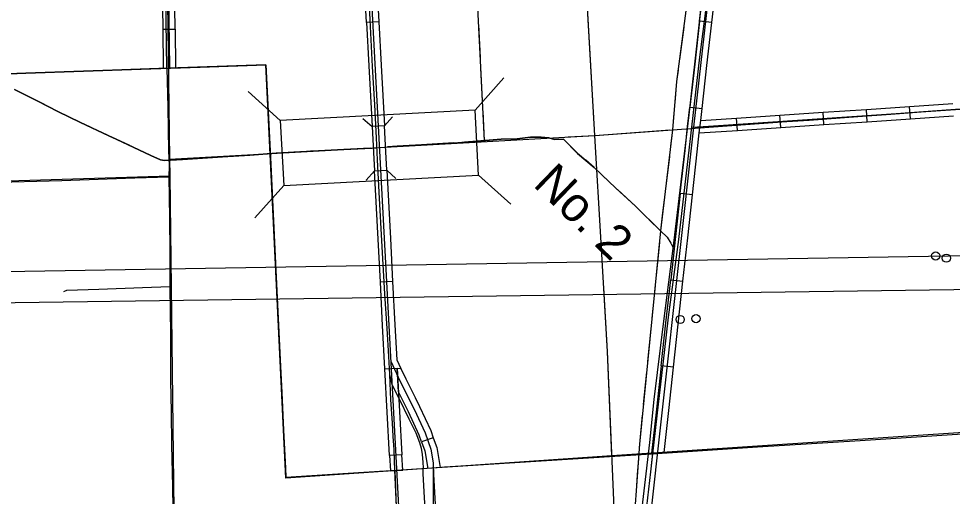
# Model space of a CAD drawing. Extents: x 646058 to 725608, y 1473014 to 1561048.
# Drawn here: x 656968 to 662655, y 1553726 to 1556632 of the extents above; entities that cross this region are included whole.
import ezdxf

# ---------------------------------------------------------------- set-up
doc = ezdxf.new("R2010")
doc.units = 0
doc.layers.add('Default', color=7, linetype='Continuous')

msp = doc.modelspace()

# ---------------------------------------------------------------- linework, layer by layer
at = {"layer": 'Default'}
for p, q in [((659161.9, 1556613.6), (659087, 1556609.6)), ((659087, 1556609.6), (659087, 1556609.6)), ((661190.6, 1556609.3), (661116.1, 1556617.8)), ((661190.6, 1556609.3), (661190.6, 1556609.3)), ((657845.8, 1556567.9), (657920.8, 1556569)), ((659747.9, 1556075.7), (659924.3, 1556272)), ((658561.5, 1556012.5), (658365.2, 1556189)), ((661056.4, 1556093.2), (661130.9, 1556084.7)), ((662136.5, 1556005.2), (662131.5, 1556080.1)), ((662399.9, 1556022.8), (662394.9, 1556097.6)), ((661346.3, 1555952.5), (661341.3, 1556027.4)), ((661609.7, 1555970.1), (661604.7, 1556044.9)), ((661873.1, 1555987.7), (661868.1, 1556062.5)), ((659158.3, 1555977.2), (659158.3, 1555977.2)), ((659172.6, 1555707.3), (659172.6, 1555707.3)), ((659172.6, 1555707.3), (659172.6, 1555707.3)), ((659172.6, 1555707.3), (659172.6, 1555707.3)), ((659172.6, 1555707.3), (659172.6, 1555707.3)), ((659172.6, 1555707.3), (659172.6, 1555707.3)), ((659172.6, 1555707.3), (659172.6, 1555707.3)), ((659172.6, 1555707.3), (659172.6, 1555707.3)), ((659768.9, 1555680.3), (659965.3, 1555503.8)), ((658582.6, 1555617.1), (658406.1, 1555420.7)), ((661072.5, 1555560.1), (660998, 1555568.3)), ((659246.2, 1555031.8), (659171.3, 1555027.8)), ((660940, 1555043.5), (661014.6, 1555035.3)), ((659199.3, 1554500.6), (659274.2, 1554504.6)), ((660956.6, 1554510.5), (660882.1, 1554518.7)), ((659493.4, 1554082), (659422.7, 1554057.1)), ((659302.3, 1553977.3), (659227.4, 1553973.3)), ((660823.4, 1553987.7), (660899.4, 1553992.7))]:
    msp.add_line(p, q, dxfattribs=at)
for points in [[(657836.4, 1559731.1), (657852.6, 1558422.3), (657853.7, 1558332.9), (657886.7, 1555776.3), (657888, 1555674.8), (657919.2, 1553129.9), (657922.4, 1553034.6), (657948.9, 1552246.6), (657964.6, 1551804.3), (657962.8, 1550661.1), (657966.7, 1550505.3), (657969.3, 1550400.1), (657996.7, 1547841.2)], [(658953.8, 1559731.1), (659024.8, 1558484.7), (659297.5, 1553362.2)], [(661474.1, 1559731.1), (661439.7, 1559417.2), (661367.6, 1558733.9), (661308.2, 1558296.7), (661244.5, 1557694.1), (661185.1, 1557210.2), (661113, 1556611.8), (661049.3, 1556047.3), (660956, 1555266.4), (660896.6, 1554791), (660837.2, 1554315.6), (660809.9, 1554053.3), (660737.8, 1553429.4)], [(660803.4, 1553465), (661080.3, 1555972.4), (661383.8, 1558638), (661511.3, 1559731.1)], [(657958.2, 1559412.7), (657923, 1559397.8), (657897.3, 1559383.2), (657874.8, 1559362.2), (657858.8, 1559337.7), (657849.4, 1559313.4), (657845.7, 1559274.7), (657858.7, 1558454.5), (657870.9, 1558422.7), (657854.2, 1558362.1), (657858, 1558328.5), (657886.7, 1556334.8)], [(660830.5, 1553984.9), (660865.7, 1554286.1), (660902.5, 1554601.2), (660927.1, 1554815.2), (660989.2, 1555288.6), (661021.8, 1555570.5), (661068, 1555972.4), (661117.1, 1556398.1), (661151.1, 1556664.1), (661188.7, 1556982.2), (661216.2, 1557225.8), (661259.5, 1557598), (661287, 1557848.1), (661328.2, 1558239.9), (661359.2, 1558512.4), (661372.2, 1558630.2)], [(660478.2, 1555921.9), (660325.5, 1558577.4)], [(661255.9, 1558579.7), (661149.5, 1557665.2), (661089.3, 1557112.2), (660975.9, 1556250.8), (660951, 1555956.5), (660877.8, 1555340.5), (660749, 1554042.3), (660702.9, 1553393.6)], [(659298.3, 1558455.1), (659610.9, 1558118.4), (659660.7, 1558057.1), (659689.4, 1558003.4), (659709.8, 1557937.6), (659713.2, 1557712.2), (659803.4, 1555890)], [(657871.2, 1556330.8), (657867.4, 1556616.5), (657867.4, 1556775.6), (657867.4, 1556951.3), (657863.6, 1557090.1), (657859.9, 1557343.5), (657856.1, 1557581.8), (657853.1, 1557835.9), (657851.6, 1557945.2), (657847, 1558131.5), (657844.8, 1558301.9), (657839.5, 1558321.5)], [(660478.2, 1555921.9), (660370.7, 1557790.5)], [(659089.9, 1556955.3), (659107.2, 1556624.8), (659121.3, 1556340.9), (659135.4, 1556106.9), (659146.2, 1555906.4), (659152.7, 1555773.1), (659162.4, 1555575.9), (659179.8, 1555243.2), (659196, 1554958.2), (659210.1, 1554746.9), (659220.9, 1554575.7), (659227.4, 1554466.2), (659241.5, 1554406.6), (659285.9, 1554318.8), (659344.5, 1554197.5), (659386.7, 1554111.9), (659410.5, 1554053.3), (659420.3, 1554018.7), (659426.8, 1553979.7), (659430, 1553934.1), (659432.1, 1553896.1)], [(659147.9, 1556877.2), (659161.9, 1556613.6)], [(661116.1, 1556617.8), (661146, 1556880.1)], [(657842, 1556831.8), (657845.8, 1556567.9)], [(657920.8, 1556569), (657917, 1556832.9)], [(659087, 1556609.6), (659073, 1556873.2)], [(661190.6, 1556609.3), (661220.5, 1556871.7)], [(659087, 1556609.6), (659101.1, 1556345.9)], [(659161.9, 1556613.6), (659176, 1556349.9)], [(659768.6, 1556594.3), (659778.4, 1556396.5)], [(661116.1, 1556617.8), (661086.2, 1556355.5)], [(661160.7, 1556347), (661190.6, 1556609.3)], [(657845.8, 1556567.9), (657849.2, 1556334.3)], [(657920.8, 1556569), (657924.2, 1556335.4)], [(661019.3, 1556580.8), (660993.5, 1556384.5)], [(665836.1, 1554301.5), (663213.3, 1554145.7), (660581.9, 1553971.7), (658595.4, 1553836.2), (658473.8, 1556351.9), (657879.5, 1556331.1), (656743.7, 1556291.4)], [(656743.7, 1556291.4), (657011.2, 1556300.7), (657713.6, 1556325.3), (658073.8, 1556337.9), (658473.8, 1556351.9), (658501.1, 1555786.6), (658515.6, 1555487.3), (658534.3, 1555101.6), (658562.6, 1554515.9), (658570.2, 1554358.2), (658581.4, 1554127.2), (658592.5, 1553896.2), (658595.1, 1553842.9), (658975.8, 1553867.1), (659204.5, 1553881.6), (659830, 1553921.3), (660344.2, 1553954), (660951, 1553992.6), (661468.1, 1554025.9), (662094.7, 1554066.2), (662560.5, 1554096.2), (663187, 1554136.5)], [(658473.8, 1556351.9), (658073.8, 1556337.9), (657713.6, 1556325.3), (657011.2, 1556300.7), (656792.7, 1556293.1)], [(657871.2, 1556330.8), (657876.4, 1556093.1), (657881.7, 1555828.5), (657884, 1555739.5), (657882.9, 1555670.5)], [(657871.2, 1556330.8), (657876.4, 1556093.1), (657881.7, 1555828.5), (657884, 1555739.5), (657882.9, 1555670.5)], [(658473.8, 1556351.9), (658501.1, 1555786.6), (658515.6, 1555487.3), (658534.3, 1555101.6), (658562.6, 1554515.9), (658581.4, 1554127.2), (658595.1, 1553842.9)], [(659101.1, 1556345.9), (659120.8, 1555975.2)], [(659176, 1556349.9), (659195.7, 1555979.2)], [(659781.6, 1556330.6), (659791.4, 1556132.8)], [(660984.8, 1556319), (660975.9, 1556250.8), (660965, 1556122.1)], [(661086.2, 1556355.5), (661056.4, 1556093.2)], [(661130.9, 1556084.7), (661160.7, 1556347)], [(659108.6, 1555844.2), (658949, 1555835.1), (658793.6, 1555828.7), (658537.1, 1555813.3), (658375.2, 1555801.1), (658209.3, 1555791.4), (657966.4, 1555775.2), (657856.4, 1555769.6), (657832.1, 1555773.6), (657773.8, 1555799.5), (657562.6, 1555898.3), (657517.2, 1555919.3), (657345.6, 1556000.3), (657206.4, 1556066.6), (657085, 1556130.6), (656941.8, 1556200.2)], [(656941.8, 1556200.2), (657085, 1556130.6), (657206.4, 1556066.6), (657345.6, 1556000.3), (657517.2, 1555919.3), (657562.6, 1555898.3), (657773.8, 1555799.5), (657832.1, 1555773.6), (657856.4, 1555769.6), (657966.4, 1555775.2), (658209.3, 1555791.4), (658375.2, 1555801.1), (658537.1, 1555813.3), (658793.6, 1555828.7), (658949, 1555835.1), (659119, 1555844.8), (659273.6, 1555855.4), (659642.7, 1555877.2), (659908.1, 1555898.3), (660003.6, 1555901.5), (660085.4, 1555911.2), (660151, 1555912), (660197.1, 1555907.2), (660231.1, 1555896.7), (660286.9, 1555899.1), (660372.7, 1555812.5), (660473.1, 1555727.5), (660605.8, 1555601.2), (660724.8, 1555490.3), (660877.8, 1555340.5), (660917.4, 1555302.5), (660940.1, 1555266.9), (660952.9, 1555241.6)], [(661080.3, 1555972.4), (663126.4, 1556108.9), (664476.5, 1556202.7), (664477.5, 1556111.4), (664473.4, 1556093.2), (664466.3, 1556074.5), (664457.6, 1556060.7), (664437.5, 1556041.2), (663835.5, 1555479), (663817, 1555457), (663805.5, 1555435.1), (663801.3, 1555418), (663800.3, 1555398.9), (663879.7, 1554193.6), (663889.9, 1554159.1), (663917.7, 1553666.2)], [(657168.4, 1556086.7), (657085, 1556130.6), (656991.7, 1556176)], [(660478.2, 1555921.9), (663119, 1556113.2)], [(661027, 1555830.7), (661043.1, 1555976.5), (661056.4, 1556093.2)], [(661067.9, 1555971.8), (661783.2, 1556014.6), (662079.9, 1556036), (662280.3, 1556051.6), (662439.8, 1556064.2), (662732.6, 1556084.7), (662958.3, 1556100.2), (663106.2, 1556109)], [(661122.7, 1556012.8), (661130.9, 1556084.7)], [(661868.1, 1556062.5), (662131.5, 1556080.1)], [(662131.5, 1556080.1), (662394.9, 1556097.6)], [(662394.9, 1556097.6), (662658.3, 1556115.2)], [(657406.1, 1555971.8), (657345.6, 1556000.3), (657227.2, 1556056.7)], [(659065, 1556025.4), (659120.8, 1555975.2)], [(659195.7, 1555979.2), (659245.9, 1556035)], [(659794.7, 1556066.9), (659803.4, 1555890)], [(660959.5, 1556056.3), (660951, 1555956.5), (660939.5, 1555859.3)], [(661122.7, 1556012.8), (661341.3, 1556027.4)], [(661341.3, 1556027.4), (661604.7, 1556044.9)], [(661604.7, 1556044.9), (661868.1, 1556062.5)], [(662136.5, 1556005.2), (662399.9, 1556022.8)], [(662399.9, 1556022.8), (662663.3, 1556040.4)], [(659195.7, 1555979.2), (659120.8, 1555975.2)], [(659120.8, 1555975.2), (659129.2, 1555818.7), (659135.2, 1555705.3)], [(659210.1, 1555709.3), (659204.1, 1555822.7), (659195.7, 1555979.2)], [(661101.5, 1555822.5), (661114.2, 1555937), (661122.7, 1556012.8)], [(661346.3, 1555952.5), (661609.7, 1555970.1)], [(661609.7, 1555970.1), (661873.1, 1555987.7)], [(661873.1, 1555987.7), (662136.5, 1556005.2)], [(657555.4, 1555901.6), (657517.2, 1555919.3), (657465.7, 1555943.6)], [(657886.7, 1555776.3), (660478.2, 1555921.9)], [(660877.8, 1555340.5), (660724.8, 1555490.3), (660605.8, 1555601.2), (660473.1, 1555727.5), (660372.7, 1555812.5), (660286.9, 1555899.1), (660231.1, 1555896.7), (660197.1, 1555907.2), (660151, 1555912), (660085.4, 1555911.2), (660003.6, 1555901.5), (659908.1, 1555898.3), (659642.7, 1555877.2), (659273.6, 1555855.4), (659214.6, 1555851.4)], [(660145.2, 1555912), (660085.4, 1555911.2), (660003.6, 1555901.5), (659947.8, 1555899.6)], [(660315.8, 1555912.8), (660478.2, 1555921.9)], [(660478.2, 1555921.9), (660933.6, 1555954.9)], [(660610.1, 1553321.4), (660554.3, 1554606.3), (660516.5, 1555268.1), (660478.2, 1555921.9)], [(661114.2, 1555937), (661346.3, 1555952.5)], [(657645.1, 1555859.7), (657562.6, 1555898.3), (657555.4, 1555901.6)], [(659355.2, 1555860.2), (659273.6, 1555855.4), (659214.6, 1555851.4)], [(659519.9, 1555870), (659421.1, 1555864.1)], [(659618.7, 1555875.8), (659519.9, 1555870)], [(659881.9, 1555896.2), (659684.5, 1555880.5)], [(660371.6, 1555813.6), (660286.9, 1555899.1), (660231.1, 1555896.7), (660210.3, 1555903.1)], [(657889.8, 1555771.3), (657856.4, 1555769.6), (657832.1, 1555773.6), (657773.8, 1555799.5), (657704.9, 1555831.7)], [(658416.8, 1555804.3), (658375.2, 1555801.1), (658219.2, 1555792)], [(658680.2, 1555821.9), (658537.1, 1555813.3), (658482.6, 1555809.2)], [(658943.9, 1555834.9), (658793.6, 1555828.7), (658746.1, 1555825.8)], [(659108.6, 1555844.2), (659009.8, 1555838.6)], [(660931.7, 1555793.8), (660908.3, 1555597.2)], [(660998, 1555568.3), (661027, 1555830.7)], [(661072.5, 1555560.1), (661101.5, 1555822.5)], [(658153.3, 1555787.7), (657966.4, 1555775.2), (657955.7, 1555774.7)], [(660568, 1555637.2), (660473.1, 1555727.5), (660421.9, 1555770.8)], [(659135.2, 1555705.3), (659085.1, 1555649.5)], [(659135.2, 1555705.3), (659210.1, 1555709.3)], [(659157.2, 1555291.4), (659135.2, 1555705.3)], [(659210.1, 1555709.3), (659232.1, 1555295.4)], [(659265.9, 1555659.1), (659210.1, 1555709.3)], [(653732.3, 1555515.5), (653800.2, 1555515), (654107.4, 1555532), (654344.2, 1555541.3), (654528.4, 1555548.2), (654865, 1555563.7), (655077, 1555572.2), (655262.7, 1555580.8), (655436.8, 1555586.2), (655707.7, 1555594.7), (655830.7, 1555596.2), (655923.6, 1555600.1), (656045, 1555604), (656446.7, 1555620.2), (656625.4, 1555628), (656926.4, 1555639.6), (657231.3, 1555648.1), (657507.6, 1555658.2), (657676.3, 1555663.6), (657882.9, 1555670.5)], [(653836.5, 1555517), (654107.4, 1555532), (654344.2, 1555541.3), (654528.4, 1555548.2), (654865, 1555563.7), (655077, 1555572.2), (655262.7, 1555580.8), (655436.8, 1555586.2), (655707.7, 1555594.7), (655830.7, 1555596.2), (655923.6, 1555600.1), (656045, 1555604), (656446.7, 1555620.2), (656625.4, 1555628), (656926.4, 1555639.6), (657231.3, 1555648.1), (657507.6, 1555658.2), (657676.3, 1555663.6), (657882.9, 1555670.5)], [(655261.9, 1555594.5), (657888, 1555674.8)], [(657882.9, 1555670.5), (657887.5, 1555419.8), (657888.3, 1555210.8), (657889.8, 1554993.3), (657892.9, 1554715.4), (657893.7, 1554428.3), (657896, 1554240.2), (657899.9, 1554036.6), (657904.5, 1553785.1), (657909.2, 1553510.3), (657915.4, 1553253.4), (657916.1, 1553169), (657920.5, 1553086.9)], [(657882.9, 1555670.5), (657887.5, 1555419.8), (657888.3, 1555210.8), (657889.8, 1554993.3), (657892.9, 1554715.4), (657893.7, 1554428.3), (657896, 1554240.2), (657899.9, 1554036.6), (657904.5, 1553785.1), (657909.2, 1553510.3), (657915.4, 1553253.4), (657916.1, 1553169), (657920.5, 1553086.9)], [(660759.9, 1555455.9), (660724.8, 1555490.3), (660615.9, 1555591.8)], [(660998, 1555568.3), (660969, 1555305.9)], [(660900.5, 1555531.7), (660888.8, 1555433.3)], [(661043.6, 1555297.7), (661072.5, 1555560.1)], [(660877.8, 1555340.5), (660807, 1555409.8)], [(660888.8, 1555433.3), (660877.8, 1555340.5), (660877.2, 1555335)], [(668379.5, 1555281.6), (649175.8, 1554963.8)], [(668379.5, 1555281.6), (649175.8, 1554963.8)], [(659171.3, 1555027.8), (659157.2, 1555291.4)], [(659232.1, 1555295.4), (659246.2, 1555031.8)], [(660969, 1555305.9), (660940, 1555043.5)], [(661014.6, 1555035.3), (661043.6, 1555297.7)], [(660870.7, 1555269.4), (660851.2, 1555072.3)], [(649175.8, 1554797.2), (668379.5, 1555063.1)], [(649175.8, 1554797.2), (668379.5, 1555063.1)], [(657242.4, 1554972.5), (657261, 1554980.7), (657456, 1554985.4), (657722.2, 1554997), (657889.8, 1555002.9)], [(659185.3, 1554764.2), (659171.3, 1555027.8)], [(659246.2, 1555031.8), (659260.2, 1554768.2)], [(660844.7, 1555006.6), (660825.1, 1554809.6)], [(660911, 1554781.1), (660940, 1555043.5)], [(660985.6, 1554772.9), (661014.6, 1555035.3)], [(660581.9, 1553971.7), (660554.3, 1554606.3), (660532.1, 1554995.1)], [(660882.1, 1554518.7), (660911, 1554781.1)], [(660956.6, 1554510.5), (660985.6, 1554772.9)], [(659199.3, 1554500.6), (659185.3, 1554764.2)], [(659260.2, 1554768.2), (659271.5, 1554556.9)], [(660818.6, 1554743.9), (660799.1, 1554546.9)], [(659234.4, 1554547.5), (659292.6, 1554424.6), (659376.7, 1554256.4), (659443.3, 1554111.3), (659478.1, 1554012.6), (659492.6, 1553928.5), (659492.6, 1553835.7), (659492.6, 1553644.2), (659491.2, 1553375.5)], [(659271.5, 1554556.9), (659296.3, 1554504.4)], [(659213.4, 1554236.9), (659199.3, 1554500.6)], [(659274.2, 1554504.6), (659288.3, 1554240.9)], [(659281.8, 1554362.3), (659274.2, 1554504.6), (659296.3, 1554504.4)], [(659296.3, 1554504.4), (659326.3, 1554441), (659383.4, 1554326.8)], [(660882.1, 1554518.7), (660853.1, 1554256.3)], [(660927.6, 1554248.1), (660956.6, 1554510.5)], [(659227.4, 1554466.2), (659233.9, 1554312.3), (659242.6, 1554173.6), (659248, 1554090.2), (659253.4, 1554010), (659255.6, 1553943.7), (659258.4, 1553885)], [(660792.5, 1554481.2), (660773, 1554284.2)], [(659316.3, 1554293.3), (659281.8, 1554362.3)], [(659383.4, 1554326.8), (659410.5, 1554272.6), (659478.1, 1554125.4), (659493.4, 1554082)], [(659422.7, 1554057.1), (659408.6, 1554097.2), (659342.8, 1554240.1), (659316.3, 1554293.3)], [(660924.3, 1553990.9), (660951, 1553992.6), (661468.1, 1554025.9), (662094.7, 1554066.2), (662560.5, 1554096.2), (663187, 1554136.5), (663575.2, 1554161.8), (664495.7, 1554221.9), (665174.2, 1554262.2), (665781.8, 1554298.3)], [(659227.4, 1553973.3), (659213.4, 1554236.9)], [(659288.3, 1554240.9), (659302.3, 1553977.3)], [(660766.5, 1554218.5), (660749, 1554042.3), (660747.5, 1554021.4)], [(660853.1, 1554256.3), (660823.4, 1553987.7)], [(660899.4, 1553992.7), (660927.6, 1554248.1)], [(659422.7, 1554057.1), (659441.7, 1554003.2), (659460.3, 1553895.2)], [(659493.4, 1554082), (659514.6, 1554022.1), (659535.5, 1553900.4), (659460.3, 1553895.2)], [(659227.4, 1553973.3), (659232.4, 1553879.7)], [(659232.4, 1553879.7), (659307.2, 1553884.8), (659302.3, 1553977.3)], [(659562.9, 1553904.4), (659830, 1553921.3), (660344.2, 1553954), (660723.7, 1553978.1)], [(660880.9, 1553328.6), (660867.8, 1553367.4), (660858.4, 1553377.5), (660787.6, 1553438.9), (660780.4, 1553456.3), (660776.8, 1553478), (660775.3, 1553504), (660788.3, 1553611.7), (660819.4, 1553874.8), (660830.8, 1553988.2)], [(660880.9, 1553328.6), (660867.8, 1553367.4), (660858.4, 1553377.5), (660787.6, 1553438.9), (660780.4, 1553456.3), (660776.8, 1553478), (660775.3, 1553504), (660788.3, 1553611.7), (660819.4, 1553874.8), (660830.5, 1553984.9)], [(660742.9, 1553955.6), (660735.8, 1553856.8)], [(658595.1, 1553842.9), (658975.8, 1553867.1), (659198.8, 1553881.2)], [(659258.4, 1553885), (659266.9, 1553661.1), (659276.2, 1553413.8), (659280.9, 1553296.4)], [(659258.5, 1553881.5), (659266.9, 1553661.1), (659276.2, 1553413.8), (659280.9, 1553296.4)], [(659464.2, 1553237.7), (659453.6, 1553488.4), (659441, 1553717.9), (659433, 1553863), (659432.1, 1553896.1)], [(659525.5, 1553306.9), (659518.1, 1553484.4), (659505.4, 1553713.9), (659497.4, 1553859), (659496.7, 1553889.3)], [(660735.8, 1553856.8), (660728.8, 1553758.1)]]:
    msp.add_lwpolyline(points, dxfattribs=at)
msp.add_lwpolyline([(659747.9, 1556075.7), (658561.5, 1556012.5), (658582.6, 1555617.1), (659768.9, 1555680.3)], close=True, dxfattribs=at)
for centre in [(662553.7, 1555188.4), (662618.7, 1555175), (660997.4, 1554801.6), (661094.3, 1554807)]:
    msp.add_circle(centre, 25, dxfattribs=at)

# ---------------------------------------------------------------- texts
msp.add_text('No. 2', height=211.2, rotation=315.9167, dxfattribs=at).set_placement((660095.6, 1555618.1))

doc.saveas('drawing.dxf')
